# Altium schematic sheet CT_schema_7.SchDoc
size 147 x 119 mm
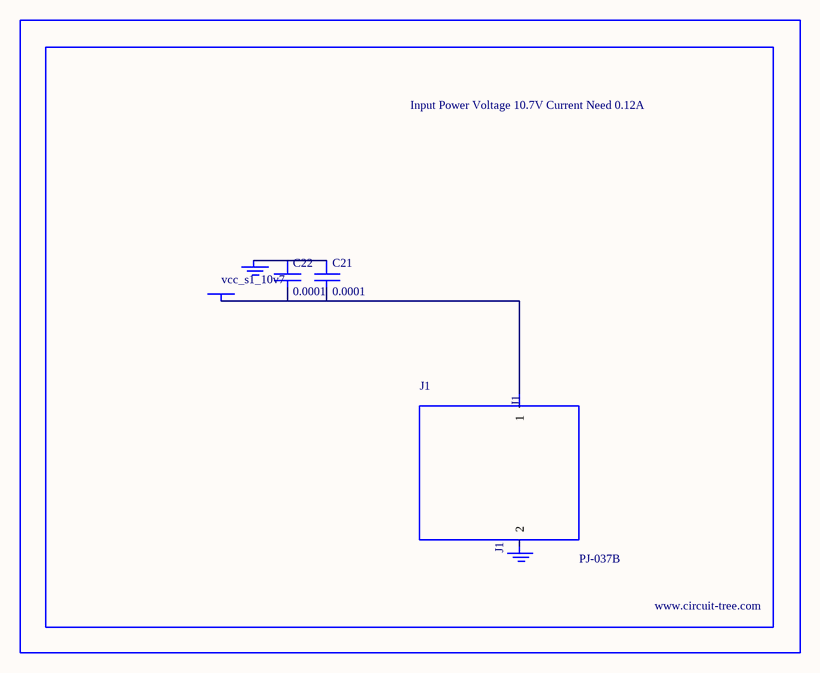
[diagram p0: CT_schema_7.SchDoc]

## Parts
BORDER6  (no value)
C21  0.0001  [EXV-9H]
C22  0.0001  [EXV-9H]
GND_INSTANCE_6_0  (no value)
GND_INSTANCE_6_1  (no value)
J1  PJ-037B  [PJ-037B_PACKAGE]
POWER_INSTANCE_6_0  vcc_s1_10v7

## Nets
NetC21_1: C21.1 C22.1 GND_INSTANCE_6_0.0(GND)
NetC21_2: C21.2 C22.2 J1.1 POWER_INSTANCE_6_0.0(PWR)

Not connected (* = marked no-connect by the designer): GND_INSTANCE_6_1 0(GND); J1 2

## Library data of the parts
BORDER6 = BORDER_PAGE6
C21 C22 = EDK107M035A9HAA
GND_INSTANCE_6_0 GND_INSTANCE_6_1 = GND
POWER_INSTANCE_6_0 = PWR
